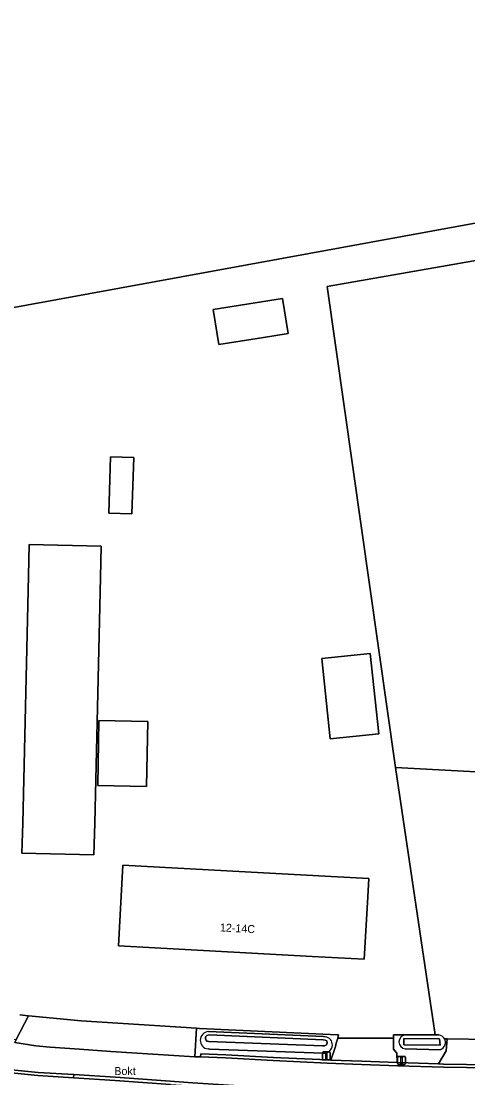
# Model space of a CAD drawing. Extents: x 162510 to 163918, y 388494 to 389774.
# Drawn here: x 162963.6 to 163019.4, y 388968.2 to 389100.2 of the extents above; entities that cross this region are included whole.
import ezdxf

# ---------------------------------------------------------------- set-up
doc = ezdxf.new("R2010")
doc.units = 0
for name, color, linetype in [('IMGEO_Afsluitpaal', 7, 'Continuous'), ('IMGEO_Erf', 7, 'Continuous'), ('IMGEO_Grasland_agrarisch', 7, 'Continuous'), ('IMGEO_Grasland_overig', 7, 'Continuous'), ('IMGEO_Oever', 7, 'Continuous'), ('IMGEO_Openbare_ruimte_label', 7, 'Continuous'), ('IMGEO_Pand', 7, 'Continuous'), ('IMGEO_Pand_nummerreeks', 7, 'Continuous'), ('IMGEO_Rijbaan_lokaal_gesloten', 7, 'Continuous'), ('IMGEO_Rijbaan_lokaal_halfverhard', 7, 'Continuous'), ('IMGEO_Rijbaan_lokaal_open', 7, 'Continuous'), ('IMGEO_Waterloop', 7, 'Continuous')]:
    doc.layers.add(name, color=color, linetype=linetype)

msp = doc.modelspace()

# ---------------------------------------------------------------- linework, layer by layer
at = {"layer": 'IMGEO_Afsluitpaal'}
for p, q in [((163001.26, 388970.5), (163001.26, 388971.3)), ((163001.26, 388971.3), (163001.26, 388970.5)), ((163001.36, 388971.4), (163002.15, 388971.4)), ((163002.15, 388971.4), (163001.36, 388971.4)), ((163002.25, 388971.3), (163002.25, 388970.5)), ((163002.25, 388970.5), (163002.25, 388971.3)), ((163010.65, 388969.95), (163010.65, 388970.75)), ((163010.65, 388970.75), (163010.65, 388969.95)), ((163010.75, 388970.85), (163011.54, 388970.85)), ((163011.54, 388970.85), (163010.75, 388970.85)), ((163011.64, 388970.75), (163011.64, 388969.95)), ((163011.64, 388969.95), (163011.64, 388970.75)), ((163002.15, 388970.4), (163001.36, 388970.4)), ((163001.36, 388970.4), (163002.15, 388970.4)), ((163011.54, 388969.85), (163010.75, 388969.85)), ((163010.75, 388969.85), (163011.54, 388969.85))]:
    msp.add_line(p, q, dxfattribs=at)
for points in [[(163001.68, 388971.28), (163001.83, 388971.28), (163001.83, 388970.53), (163001.68, 388970.53), (163001.68, 388971.28)], [(163011.07, 388970.72), (163011.22, 388970.72), (163011.22, 388969.97), (163011.07, 388969.97), (163011.07, 388970.72)]]:
    msp.add_lwpolyline(points, dxfattribs=at)
for centre, start, end in [((163001.36, 388971.3), 90, 180), ((163001.36, 388971.3), 90, 180), ((163001.36, 388970.5), 180, 270), ((163001.36, 388970.5), 180, 270), ((163002.15, 388971.3), 0, 90), ((163002.15, 388971.3), 360, 90), ((163002.15, 388970.5), 270, 0), ((163002.15, 388970.5), 270, 0), ((163010.75, 388970.75), 90, 180), ((163010.75, 388970.75), 90, 180), ((163011.54, 388970.75), 0, 90), ((163011.54, 388970.75), 360, 90), ((163010.75, 388969.95), 180, 270), ((163010.75, 388969.95), 180, 270), ((163011.54, 388969.95), 270, 0), ((163011.54, 388969.95), 270, 0)]:
    msp.add_arc(centre, 0.1, start, end, dxfattribs=at)
at = {"layer": 'IMGEO_Erf'}
for points in [[(162917.44, 389109.24), (162918.81, 389099.65), (162919.73, 389094.6), (162907.75, 389092.44), (162907.84, 389092.21), (162880.03, 389087.17), (162881.79, 389060.3), (162882.42, 389049.74), (163026.73, 389076.11)], [(163026.73, 389076.11), (162882.42, 389049.74)], [(163001.87, 389067.02), (163025.18, 389071.12)], [(162963.46, 388976.02), (162964.53, 388975.92), (162971.11, 388975.28), (162985.53, 388974.35), (162985.89, 388974.33), (163003.13, 388973.54), (163003.27, 388973.53), (163003.18, 388973.13), (163010.13, 388973.11), (163010.13, 388973.53), (163011.6, 388973.53), (163015.35, 388973.53), (163010.38, 389006.95), (163001.87, 389067.02)], [(163021.58, 388990.68), (163030.06, 388990.43), (163029.52, 388987.73), (163034.42, 388987.07), (163034.69, 388990.29), (163042.33, 388990.07), (163043.41, 389002.45), (163032.54, 389003.17), (163032.96, 389007.33), (163026.62, 389007.47), (163026.66, 389006.08), (163010.38, 389006.95), (163015.35, 388973.53), (163015.83, 388973.53)], [(163016.52, 388973.04), (163016.85, 388973.03), (163022.23, 388972.97), (163021.97, 388975.96), (163021.58, 388990.68)]]:
    msp.add_lwpolyline(points, dxfattribs=at)
for points in [[(162987.62, 389064.16), (162996.27, 389065.54), (162996.97, 389061.15), (162993.66, 389060.62), (162988.32, 389059.77)], [(162974.56, 389038.72), (162974.79, 389045.74), (162977.68, 389045.65), (162977.45, 389038.62)], [(162964.61, 389034.78), (162973.6, 389034.57), (162973.51, 389030.67), (162972.8, 389000), (162972.71, 388996.01), (162963.71, 388996.22), (162963.8, 389000), (162964.52, 389030.88)], [(163001.17, 389020.57), (163007.25, 389021.2), (163008.3, 389011.15), (163002.22, 389010.52)], [(162979.45, 389012.69), (162979.28, 389004.56), (162973.2, 389004.68), (162973.3, 389012.82)], [(163007.05, 388993.06), (163006.92, 388990.76), (163006.5, 388982.97), (163000, 388983.32), (162991.67, 388983.77), (162975.77, 388984.64), (162976.32, 388994.73), (162991.62, 388993.9), (163002.37, 388993.32)]]:
    msp.add_lwpolyline(points, close=True, dxfattribs=at)
msp.add_arc((163015.68, 388972.58), 0.958, 28.6014, 81.1711, dxfattribs=at)
at = {"layer": 'IMGEO_Grasland_agrarisch'}
msp.add_lwpolyline([(163025.18, 389071.12), (163001.87, 389067.02), (163010.38, 389006.95), (163026.66, 389006.08)], dxfattribs=at)
at = {"layer": 'IMGEO_Grasland_overig'}
for points in [[(162953.12, 388973.99), (162956.93, 388973.53), (162963, 388972.94), (162964.53, 388975.92), (162963.46, 388976.02)], [(162987.02, 388973.95), (163001.38, 388973.31), (163001.62, 388973.3)], [(163011.6, 388973.53), (163010.13, 388973.53), (163010.13, 388973.11), (163010.13, 388972.36), (163010.13, 388971.73), (163010.57, 388971.25), (163010.59, 388970.07), (163010.71, 388970.07), (163015.79, 388969.91), (163016.72, 388971.54), (163016.85, 388973.03), (163016.52, 388973.04)], [(162970.16, 388968.16), (162965.69, 388968.45), (162953.24, 388969.71), (162947.11, 388970.58)], [(163001.51, 388971.26), (163001.35, 388971.26), (162987.19, 388971.76), (162986.98, 388971.77)], [(163016.02, 388971.68), (163011.61, 388971.78)]]:
    msp.add_lwpolyline(points, dxfattribs=at)
msp.add_lwpolyline([(163003, 388972.51), (163003.18, 388973.13), (163003.27, 388973.53), (163003.13, 388973.54), (162985.89, 388974.33), (162985.53, 388974.35), (162985.33, 388970.8), (162986.02, 388970.77), (162986.05, 388971.17), (162989.18, 388971.05), (162995.14, 388970.72), (163001.89, 388970.41), (163002.33, 388970.39), (163002.88, 388972.07)], close=True, dxfattribs=at)
for centre, radius, start, end in [((162987.08, 388972.86), 1.09, 93.1927, 264.6484), ((163001.48, 388972.28), 1.03, 271.6979, 82.25), ((163011.7, 388972.65), 0.877, 96.5539, 264.2345), ((163015.68, 388972.58), 0.956, 290.548, 28.7948)]:
    msp.add_arc(centre, radius, start, end, dxfattribs=at)
at = {"layer": 'IMGEO_Oever'}
for points in [[(163001.37, 388972.91), (163001.61, 388972.88), (163001.8, 388972.78), (163001.86, 388972.55), (163001.78, 388972.3), (163001.53, 388972.16), (163001.29, 388972.16), (162987.05, 388972.69), (162986.82, 388972.73), (162986.72, 388972.87), (162986.65, 388973.07), (162986.65, 388973.3), (162986.81, 388973.44), (162987.11, 388973.52)], [(163015.98, 388972.25), (163011.44, 388972.28), (163011.42, 388973.06), (163015.88, 388973.04)]]:
    msp.add_lwpolyline(points, close=True, dxfattribs=at)
for points in [[(163001.62, 388973.3), (163001.38, 388973.31), (162987.02, 388973.95)], [(163015.83, 388973.53), (163015.35, 388973.53), (163011.6, 388973.53)], [(162986.98, 388971.77), (162987.19, 388971.76), (163001.35, 388971.26), (163001.51, 388971.26)], [(163011.61, 388971.78), (163016.02, 388971.68)]]:
    msp.add_lwpolyline(points, dxfattribs=at)
for centre, radius, start, end in [((162987.08, 388972.86), 1.09, 93.1927, 264.6484), ((163001.48, 388972.28), 1.03, 271.6979, 82.25), ((163011.7, 388972.65), 0.877, 96.5539, 264.2345), ((163015.68, 388972.58), 0.958, 28.6014, 81.1711), ((163015.68, 388972.58), 0.956, 290.548, 28.7948)]:
    msp.add_arc(centre, radius, start, end, dxfattribs=at)
at = {"layer": 'IMGEO_Pand'}
for points in [[(162987.62, 389064.16), (162988.32, 389059.77), (162993.66, 389060.62), (162996.97, 389061.15), (162996.27, 389065.54)], [(162974.56, 389038.72), (162977.45, 389038.62), (162977.68, 389045.65), (162974.79, 389045.74)], [(162973.51, 389030.67), (162973.6, 389034.57), (162964.61, 389034.78), (162964.52, 389030.88), (162963.8, 389000), (162963.71, 388996.22), (162972.71, 388996.01), (162972.8, 389000)], [(163001.17, 389020.57), (163002.22, 389010.52), (163008.3, 389011.15), (163007.25, 389021.2)], [(162979.28, 389004.56), (162979.45, 389012.69), (162973.3, 389012.82), (162973.2, 389004.68)], [(163006.92, 388990.76), (163007.05, 388993.06), (163002.37, 388993.32), (162991.62, 388993.9), (162976.32, 388994.73), (162975.77, 388984.64), (162991.67, 388983.77), (163000, 388983.32), (163006.5, 388982.97)]]:
    msp.add_lwpolyline(points, close=True, dxfattribs=at)
at = {"layer": 'IMGEO_Rijbaan_lokaal_gesloten'}
for points in [[(163060.66, 388969.22), (163043.39, 388969.28), (163026.88, 388969.34), (163019.27, 388969.44), (163016.38, 388969.49), (163010.69, 388969.67), (163006.16, 388969.85), (163001.87, 388970.01), (162995.11, 388970.32), (162989.16, 388970.65), (162986.02, 388970.77), (162985.33, 388970.8), (162980.07, 388971.13), (162974.83, 388971.46), (162970.89, 388971.74), (162967.25, 388972), (162965.45, 388972.17), (162962.8, 388972.56), (162960.47, 388972.81), (162956.88, 388973.14), (162953.08, 388973.59)], [(162947.16, 388970.98), (162953.29, 388970.1), (162965.73, 388968.84), (162970.17, 388968.56), (162975.39, 388968.23), (162985.05, 388967.56), (162990.8, 388967.16), (162991.48, 388967.11), (163004.85, 388966.44), (163005.32, 388966.41), (163012.76, 388966.27), (163018.45, 388966.14), (163027.25, 388966.03), (163035.82, 388966), (163049.06, 388965.83), (163059.25, 388965.85), (163068.57, 388965.9)]]:
    msp.add_lwpolyline(points, dxfattribs=at)
at = {"layer": 'IMGEO_Rijbaan_lokaal_halfverhard'}
for points in [[(162947.11, 388970.58), (162953.24, 388969.71), (162965.69, 388968.45), (162970.16, 388968.16), (162970.17, 388968.56), (162965.73, 388968.84), (162953.29, 388970.1), (162947.16, 388970.98)], [(163024.23, 388969.78), (163019.28, 388969.84), (163016.39, 388969.89), (163015.79, 388969.91), (163010.71, 388970.07), (163010.59, 388970.07), (163006.18, 388970.25), (163002.33, 388970.39), (163001.89, 388970.41), (162995.14, 388970.72), (162989.18, 388971.05), (162986.05, 388971.17), (162986.02, 388970.77), (162989.16, 388970.65), (162995.11, 388970.32), (163001.87, 388970.01), (163006.16, 388969.85), (163010.69, 388969.67), (163016.38, 388969.49), (163019.27, 388969.44), (163026.88, 388969.34), (163043.39, 388969.28), (163060.66, 388969.22)], [(162982.29, 388967.35), (162975.36, 388967.83), (162970.16, 388968.16)]]:
    msp.add_lwpolyline(points, dxfattribs=at)
msp.add_lwpolyline([(162970.17, 388968.56), (162970.16, 388968.16), (162975.36, 388967.83), (162982.29, 388967.35), (162985.03, 388967.16), (162990.78, 388966.76), (162990.8, 388967.16), (162985.05, 388967.56), (162975.39, 388968.23)], close=True, dxfattribs=at)
at = {"layer": 'IMGEO_Rijbaan_lokaal_open'}
for points in [[(162985.53, 388974.35), (162971.11, 388975.28), (162964.53, 388975.92), (162963, 388972.94), (162962.8, 388972.56), (162965.45, 388972.17), (162967.25, 388972), (162970.89, 388971.74), (162974.83, 388971.46), (162980.07, 388971.13), (162985.33, 388970.8)], [(163010.13, 388971.73), (163010.13, 388972.36), (163010.13, 388973.11), (163003.18, 388973.13), (163003, 388972.51), (163002.88, 388972.07), (163002.33, 388970.39), (163006.18, 388970.25), (163010.59, 388970.07), (163010.57, 388971.25)], [(163022.31, 388971.93), (163022.23, 388972.97), (163016.85, 388973.03), (163016.72, 388971.54), (163015.79, 388969.91), (163016.39, 388969.89), (163019.28, 388969.84), (163024.23, 388969.78)]]:
    msp.add_lwpolyline(points, close=True, dxfattribs=at)
at = {"layer": 'IMGEO_Waterloop'}
for points in [[(162987.05, 388972.69), (163001.29, 388972.16), (163001.53, 388972.16), (163001.78, 388972.3), (163001.86, 388972.55), (163001.8, 388972.78), (163001.61, 388972.88), (163001.37, 388972.91), (162987.11, 388973.52), (162986.81, 388973.44), (162986.65, 388973.3), (162986.65, 388973.07), (162986.72, 388972.87), (162986.82, 388972.73)], [(163015.88, 388973.04), (163011.42, 388973.06), (163011.44, 388972.28), (163015.98, 388972.25)]]:
    msp.add_lwpolyline(points, close=True, dxfattribs=at)

# ---------------------------------------------------------------- texts
at = {"layer": 'IMGEO_Openbare_ruimte_label'}
msp.add_text('Bokt', height=1, dxfattribs=at).set_placement((162975.25, 388968.51))
at = {"layer": 'IMGEO_Pand_nummerreeks'}
msp.add_text('12-14C', height=1, rotation=356.8946, dxfattribs=at).set_placement((162988.43, 388986.47))

doc.saveas('drawing.dxf')
